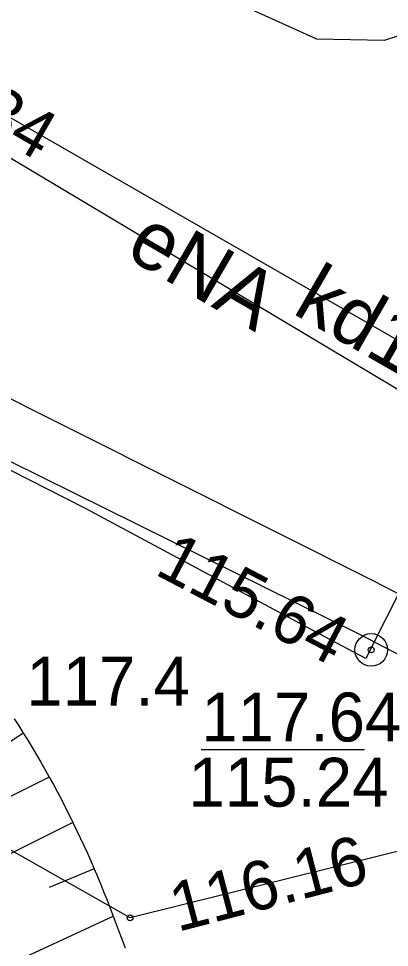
# Model space of a CAD drawing. Extents: x 6434771 to 6436222, y 5663454 to 5664782.
# Drawn here: x 6435398.53 to 6435404.21, y 5663731.68 to 5663745.93 of the extents above; entities that cross this region are included whole.
import ezdxf

# ---------------------------------------------------------------- set-up
doc = ezdxf.new("R2010")
doc.units = 0
for name, color, linetype in [('Warstwa 10', 7, 'Continuous'), ('Warstwa 12', 7, 'Continuous'), ('Warstwa 13', 7, 'Continuous'), ('Warstwa 14', 7, 'Continuous'), ('Warstwa 2', 7, 'Continuous'), ('Warstwa 20', 7, 'Continuous'), ('Warstwa 4', 7, 'Continuous'), ('Warstwa 6', 7, 'Continuous'), ('Warstwa 7', 7, 'Continuous')]:
    doc.layers.add(name, color=color, linetype=linetype)

msp = doc.modelspace()

# ---------------------------------------------------------------- linework, layer by layer
at = {"layer": 'Warstwa 10'}
for p, q in [((6435398.457, 5663735.189), (6435398.528, 5663735.079)), ((6435398.528, 5663735.079), (6435398.599, 5663734.968)), ((6435398.598, 5663734.968), (6435397.131, 5663733.98)), ((6435398.599, 5663734.968), (6435398.667, 5663734.858)), ((6435398.667, 5663734.858), (6435398.735, 5663734.746)), ((6435398.735, 5663734.746), (6435398.802, 5663734.633)), ((6435398.802, 5663734.633), (6435398.867, 5663734.52)), ((6435398.867, 5663734.52), (6435398.933, 5663734.407)), ((6435398.933, 5663734.407), (6435398.997, 5663734.294)), ((6435398.997, 5663734.293), (6435398.319, 5663733.956)), ((6435398.997, 5663734.294), (6435399.059, 5663734.179)), ((6435399.059, 5663734.179), (6435399.122, 5663734.064)), ((6435399.122, 5663734.064), (6435399.182, 5663733.948)), ((6435399.182, 5663733.948), (6435399.242, 5663733.832)), ((6435399.242, 5663733.832), (6435399.302, 5663733.716)), ((6435399.359, 5663733.598), (6435397.814, 5663732.828)), ((6435399.302, 5663733.716), (6435399.359, 5663733.598)), ((6435399.359, 5663733.598), (6435399.416, 5663733.48)), ((6435399.416, 5663733.48), (6435399.472, 5663733.363)), ((6435399.472, 5663733.363), (6435399.527, 5663733.244)), ((6435399.527, 5663733.244), (6435399.581, 5663733.125)), ((6435399.581, 5663733.125), (6435399.634, 5663733.006)), ((6435399.686, 5663732.885), (6435398.994, 5663732.599)), ((6435399.634, 5663733.006), (6435399.686, 5663732.885)), ((6435399.686, 5663732.885), (6435399.736, 5663732.766)), ((6435399.736, 5663732.766), (6435399.787, 5663732.644)), ((6435399.787, 5663732.644), (6435399.835, 5663732.523)), ((6435399.835, 5663732.523), (6435399.883, 5663732.402)), ((6435399.883, 5663732.402), (6435399.929, 5663732.279)), ((6435399.929, 5663732.279), (6435399.975, 5663732.157)), ((6435398.568, 5663731.503), (6435399.975, 5663732.157)), ((6435399.975, 5663732.157), (6435400.02, 5663732.035)), ((6435400.02, 5663732.035), (6435400.066, 5663731.915)), ((6435400.066, 5663731.915), (6435400.113, 5663731.795)), ((6435400.113, 5663731.795), (6435400.161, 5663731.674))]:
    msp.add_line(p, q, dxfattribs=at)
at = {"layer": 'Warstwa 12'}
for points in [[(6435427.17, 5663739.193), (6435426.34, 5663739.17), (6435421.79, 5663741.74), (6435415.76, 5663730.22), (6435403.78, 5663736.47), (6435393.01, 5663741.8), (6435387.55, 5663744.3), (6435376.19, 5663748.47), (6435370.47, 5663750.27), (6435364.67, 5663752.32), (6435359.09, 5663754.45), (6435353.66, 5663756.84), (6435348.17, 5663759.42), (6435342.78, 5663762.07), (6435335.44, 5663765.94), (6435331.63, 5663758.95), (6435324.69, 5663762.75), (6435328.9, 5663769.89), (6435296.25, 5663788.25), (6435294.655, 5663789.682)], [(6435427.17, 5663739.193), (6435426.57, 5663739.84), (6435421.37, 5663742.74), (6435415.39, 5663731.39), (6435403.97, 5663737.3), (6435393.25, 5663742.68), (6435387.83, 5663745.16), (6435382.26, 5663747.43), (6435376.45, 5663749.28), (6435370.72, 5663751.07), (6435365.02, 5663753.03), (6435359.55, 5663755.18), (6435354, 5663757.65), (6435348.62, 5663760.2), (6435343.16, 5663762.85), (6435335.14, 5663767.04), (6435331.28, 5663760.06), (6435325.83, 5663763.09), (6435330, 5663770.22), (6435296.67, 5663789), (6435294.655, 5663789.682)], [(6435427.118, 5663723.068), (6435426.68, 5663723.244), (6435428.372, 5663725.873), (6435386.59, 5663750.859), (6435384.11, 5663746.789), (6435368.423, 5663752.919), (6435363.517, 5663745.478), (6435363.43, 5663745.55)], [(6435426.817, 5663721.789), (6435404.909, 5663733.297), (6435400.235, 5663732.133), (6435395.556, 5663734.79), (6435378.025, 5663745.196)]]:
    msp.add_lwpolyline(points, dxfattribs=at)
at = {"layer": 'Warstwa 14'}
msp.add_line((6435401.327, 5663734.715), (6435403.829, 5663734.715), dxfattribs=at)
for centre in [(6435403.933, 5663736.246), (6435403.933, 5663736.246), (6435400.235, 5663732.133)]:
    msp.add_circle(centre, 0.045, dxfattribs=at)
at = {"layer": 'Warstwa 2'}
msp.add_lwpolyline([(6435402.82, 5663750.703), (6435403.614, 5663750.816), (6435404.363, 5663750.685), (6435405.105, 5663750.286), (6435405.662, 5663749.785), (6435406.087, 5663749.055), (6435406.241, 5663748.406), (6435406.171, 5663747.493), (6435405.951, 5663746.931), (6435405.464, 5663746.287), (6435404.788, 5663745.814), (6435404.132, 5663745.6), (6435403.098, 5663745.62), (6435402.148, 5663746.047), (6435401.402, 5663746.89), (6435401.095, 5663747.854), (6435401.093, 5663748.747), (6435401.358, 5663749.504), (6435401.961, 5663750.238), (6435402.82, 5663750.703)], dxfattribs=at)
at = {"layer": 'Warstwa 20'}
for p, q in [((6435398.457, 5663735.189), (6435398.528, 5663735.079)), ((6435398.528, 5663735.079), (6435398.599, 5663734.968)), ((6435398.599, 5663734.968), (6435398.667, 5663734.858)), ((6435398.667, 5663734.858), (6435398.735, 5663734.746)), ((6435398.735, 5663734.746), (6435398.802, 5663734.633)), ((6435398.802, 5663734.633), (6435398.867, 5663734.52)), ((6435398.867, 5663734.52), (6435398.933, 5663734.407)), ((6435398.933, 5663734.407), (6435398.997, 5663734.294)), ((6435398.997, 5663734.294), (6435399.059, 5663734.179)), ((6435399.059, 5663734.179), (6435399.122, 5663734.064)), ((6435399.122, 5663734.064), (6435399.182, 5663733.948)), ((6435399.182, 5663733.948), (6435399.242, 5663733.832)), ((6435399.242, 5663733.832), (6435399.302, 5663733.716)), ((6435399.302, 5663733.716), (6435399.359, 5663733.598)), ((6435399.359, 5663733.598), (6435399.416, 5663733.48)), ((6435399.416, 5663733.48), (6435399.472, 5663733.363)), ((6435399.472, 5663733.363), (6435399.527, 5663733.244)), ((6435399.527, 5663733.244), (6435399.581, 5663733.125)), ((6435399.581, 5663733.125), (6435399.634, 5663733.006)), ((6435399.634, 5663733.006), (6435399.686, 5663732.885)), ((6435399.686, 5663732.885), (6435399.736, 5663732.766)), ((6435399.736, 5663732.766), (6435399.787, 5663732.644)), ((6435399.787, 5663732.644), (6435399.835, 5663732.523)), ((6435399.835, 5663732.523), (6435399.883, 5663732.402)), ((6435399.883, 5663732.402), (6435399.929, 5663732.279)), ((6435399.929, 5663732.279), (6435399.975, 5663732.157)), ((6435399.975, 5663732.157), (6435400.02, 5663732.035)), ((6435400.02, 5663732.035), (6435400.066, 5663731.915)), ((6435400.066, 5663731.915), (6435400.113, 5663731.795)), ((6435400.113, 5663731.795), (6435400.161, 5663731.674))]:
    msp.add_line(p, q, dxfattribs=at)
at = {"layer": 'Warstwa 4'}
msp.add_circle((6435403.933, 5663736.246), 0.25, dxfattribs=at)
at = {"layer": 'Warstwa 6'}
msp.add_circle((6435403.933, 5663736.246), 0.045, dxfattribs=at)
at = {"layer": 'Warstwa 7'}
for points in [[(6435446.608, 5663727.092), (6435435.669, 5663732.84), (6435427.996, 5663737.007), (6435423.858, 5663739.204), (6435414.565, 5663744.159), (6435409.401, 5663746.809), (6435406.948, 5663742.261), (6435403.848, 5663736.111), (6435403.219, 5663736.445), (6435399.552, 5663738.418), (6435393.792, 5663741.346), (6435390.125, 5663743.291), (6435391.08, 5663745.546), (6435392.052, 5663748.284)], [(6435419.418, 5663717.351), (6435420.754, 5663720.325), (6435425.477, 5663728.829), (6435425.72, 5663728.89), (6435425.6, 5663729.29), (6435419.2, 5663732.48), (6435414.45, 5663735.18), (6435395.25, 5663746.23)]]:
    msp.add_lwpolyline(points, dxfattribs=at)

# ---------------------------------------------------------------- texts
at = {"layer": 'Warstwa 13'}
msp.add_text('eNA', height=0.9, rotation=329.8117, dxfattribs=at).set_placement((6435400.134, 5663742.294))
msp.add_text('117.4', height=0.75, dxfattribs=at).set_placement((6435398.644, 5663735.392))
at = {"layer": 'Warstwa 14'}
for s, rotation, p in [('116.34', 330.081, (6435396.156, 5663745.275)), ('115.64', 332.4072, (6435400.594, 5663737.415)), ('116.16', 14.6734, (6435400.964, 5663731.915))]:
    msp.add_text(s, height=0.75, rotation=rotation, dxfattribs=at).set_placement(p)
msp.add_text('115.24', height=0.75, dxfattribs=at).set_placement((6435401.13, 5663733.84))
at = {"layer": 'Warstwa 6'}
msp.add_text('117.64', height=0.75, dxfattribs=at).set_placement((6435401.326, 5663734.84))
at = {"layer": 'Warstwa 7'}
msp.add_text('kd160', height=0.9, rotation=330.081, dxfattribs=at).set_placement((6435402.703, 5663741.421))

doc.saveas('drawing.dxf')
